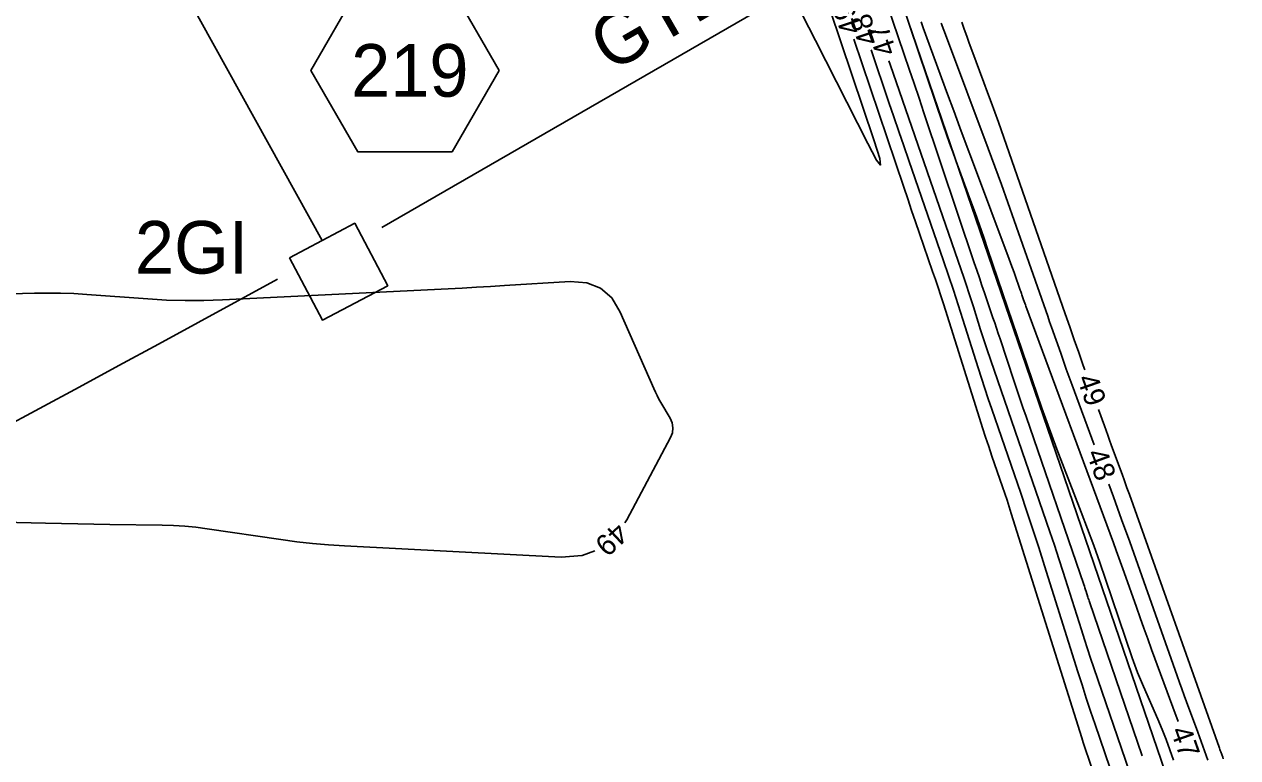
# Model space of a CAD drawing. Extents: x 2384780 to 2405861, y 547869 to 573706.
# Drawn here: x 2391704.7 to 2391820.1, y 552887.6 to 552957.3 of the extents above; entities that cross this region are included whole.
import ezdxf

# ---------------------------------------------------------------- set-up
doc = ezdxf.new("R2010")
doc.units = 0
for name, color, linetype in [('Breaklines', 7, 'Continuous'), ('Old_Level_12', 7, 'Continuous'), ('Old_Level_5', 7, 'Continuous'), ('Old_Level_60', 7, 'Continuous'), ('Old_Level_61', 7, 'Continuous'), ('Sheet Plan CELL', 7, 'Continuous')]:
    doc.layers.add(name, color=color, linetype=linetype)

msp = doc.modelspace()

# ---------------------------------------------------------------- linework, layer by layer
at = {"layer": 'Breaklines'}
for p, q in [((2391820.056, 552866.099), (2391754.1115, 553058.7325)), ((2391733.0265, 552936.75525), (2391691.145, 553012.541))]:
    msp.add_line(p, q, dxfattribs=at)
msp.add_lwpolyline([(2391729.92225, 552935.11175), (2391736.13075, 552938.39875), (2391739.2715, 552932.4665), (2391733.06825, 552929.1965)], close=True, dxfattribs=at)
at = {"layer": 'Old_Level_12'}
msp.add_lwpolyline([(2391749.86575, 552952.93425), (2391745.39125, 552960.68425), (2391736.44225, 552960.68425), (2391731.96775, 552952.93425), (2391736.44225, 552945.18425), (2391745.39125, 552945.18425)], close=True, dxfattribs=at)
at = {"layer": 'Old_Level_5'}
msp.add_arc((2390350.00532, 555442.22291), 2863, 287.79675278, 298.78936111, dxfattribs=at)
at = {"layer": 'Old_Level_60'}
for points in [[(2391786.1685, 552960.912), (2391788.366, 552954.45175), (2391788.83625, 552953.067), (2391789.30475, 552951.682), (2391789.772, 552950.29625), (2391790.23775, 552948.91025), (2391795.01825, 552934.655), (2391795.26025, 552933.93475), (2391795.503, 552933.215), (2391795.7465, 552932.49525), (2391795.99075, 552931.77575), (2391796.79, 552929.42625), (2391796.961, 552928.92275), (2391797.13075, 552928.41875), (2391797.29975, 552927.9145), (2391797.46775, 552927.41), (2391798.78525, 552923.4405), (2391799.0685, 552922.59025), (2391799.35425, 552921.74075), (2391799.64225, 552920.892), (2391799.93275, 552920.044), (2391805.42875, 552904.05975), (2391805.48475, 552903.89525), (2391805.5395, 552903.7305), (2391805.59325, 552903.565), (2391805.646, 552903.3995), (2391805.816, 552902.858), (2391805.85275, 552902.742), (2391805.8905, 552902.62625), (2391805.92875, 552902.51075), (2391805.96775, 552902.3955), (2391810.9695, 552887.7755)], [(2391813.94775, 552887.3565), (2391813.61575, 552888.343), (2391813.258, 552889.32), (2391812.87475, 552890.28725), (2391812.46625, 552891.24475), (2391811.08975, 552894.35675), (2391810.80225, 552895.0265), (2391810.53, 552895.702), (2391810.27275, 552896.38375), (2391810.0305, 552897.07125), (2391807.487, 552904.55525), (2391806.93425, 552906.15625), (2391806.36575, 552907.7515), (2391805.78175, 552909.34125), (2391805.18225, 552910.92525), (2391802.87275, 552916.93925), (2391802.384, 552918.23025), (2391801.908, 552919.526), (2391801.44475, 552920.826), (2391800.99425, 552922.13075), (2391796.3195, 552935.88275), (2391795.91625, 552937.057), (2391795.50575, 552938.22875), (2391795.08775, 552939.398), (2391794.6625, 552940.5645), (2391793.26125, 552944.37125), (2391792.96375, 552945.18775), (2391792.671, 552946.00625), (2391792.38375, 552946.8265), (2391792.10125, 552947.6485), (2391788.877, 552957.1325)], [(2391814.3855, 552891.0375), (2391813.8895, 552892.39975), (2391811.87525, 552897.88325), (2391811.50825, 552898.8865), (2391811.144, 552899.891), (2391810.78275, 552900.89625), (2391810.424, 552901.9025), (2391809.25725, 552905.1915), (2391809.006, 552905.896), (2391808.7525, 552906.5995), (2391808.49675, 552907.30225), (2391808.23875, 552908.00425), (2391799.9245, 552930.51225), (2391799.8695, 552930.662), (2391799.81525, 552930.81175), (2391799.76175, 552930.962), (2391799.709, 552931.11225), (2391799.53725, 552931.60375), (2391799.5005, 552931.70925), (2391799.46375, 552931.8145), (2391799.427, 552931.91975), (2391799.39025, 552932.02525), (2391798.833, 552933.621), (2391798.7125, 552933.96275), (2391798.59025, 552934.3035), (2391798.466, 552934.64375), (2391798.34, 552934.98325), (2391794.84525, 552944.3085), (2391794.2505, 552945.899), (2391793.658, 552947.4905), (2391793.068, 552949.0825), (2391792.48025, 552950.67575), (2391790.1635, 552956.97), (2391789.95525, 552957.5415)], [(2391806.40625, 552917.351), (2391804.312, 552923.02025), (2391804.03575, 552923.77325), (2391803.76275, 552924.5275), (2391803.4935, 552925.283), (2391803.22725, 552926.0395), (2391802.36375, 552928.513), (2391802.17875, 552929.04325), (2391801.9935, 552929.57325), (2391801.8085, 552930.10325), (2391801.6235, 552930.63325), (2391798.81975, 552938.6635), (2391798.21425, 552940.3825), (2391797.59875, 552942.098), (2391796.97375, 552943.81), (2391796.339, 552945.51825), (2391792.37875, 552956.08575), (2391791.88375, 552957.41725)], [(2391805.52, 552924.4775), (2391805.38, 552924.87875), (2391804.95175, 552926.10525), (2391804.5235, 552927.332), (2391804.09525, 552928.5585), (2391803.667, 552929.785), (2391797.306, 552948.00375), (2391796.9715, 552948.95325), (2391796.6315, 552949.901), (2391796.28625, 552950.84675), (2391795.9355, 552951.7905), (2391794.78125, 552954.8705), (2391794.53575, 552955.531), (2391794.29375, 552956.193), (2391794.0555, 552956.85625), (2391793.82075, 552957.52075)], [(2391783.563, 552955.91025), (2391788.3155, 552941.8295), (2391788.6885, 552940.727), (2391789.06375, 552939.625), (2391789.4405, 552938.5235), (2391789.81925, 552937.42275), (2391791.05925, 552933.82775), (2391791.3225, 552933.05675), (2391791.5805, 552932.28375), (2391791.8335, 552931.50925), (2391792.08125, 552930.733), (2391795.51125, 552919.86875), (2391795.79975, 552918.96525), (2391796.094, 552918.0635), (2391796.39375, 552917.16375), (2391796.69925, 552916.26575), (2391797.707, 552913.3355), (2391797.92075, 552912.707), (2391798.13025, 552912.077), (2391798.3355, 552911.4455), (2391798.5365, 552910.81275), (2391805.2335, 552889.49), (2391805.38125, 552889.02475), (2391805.532, 552888.5605), (2391805.6855, 552888.097), (2391805.842, 552887.63475), (2391806.35825, 552886.12575)], [(2391785.22425, 552954.89275), (2391786.91075, 552949.8955), (2391787.37875, 552948.51275), (2391787.84925, 552947.13075), (2391788.32175, 552945.7495), (2391788.79675, 552944.369), (2391792.08775, 552934.82825), (2391792.563, 552933.43525), (2391793.02925, 552932.0395), (2391793.486, 552930.6405), (2391793.93375, 552929.2385), (2391795.38125, 552924.65375), (2391795.6945, 552923.67225), (2391796.014, 552922.693), (2391796.33975, 552921.7155), (2391796.6715, 552920.74025), (2391799.426, 552912.72975), (2391800.01025, 552911.0115), (2391800.58325, 552909.28925), (2391801.1445, 552907.56325), (2391801.69425, 552905.83325), (2391804.856, 552895.766), (2391805.2555, 552894.508), (2391805.66275, 552893.25275), (2391806.07825, 552892), (2391806.5015, 552890.75), (2391807.89725, 552886.6705)], [(2391786.90275, 552953.842), (2391787.01925, 552953.50375), (2391794.04425, 552933.138), (2391794.27225, 552932.47025), (2391794.49575, 552931.801), (2391794.71475, 552931.13025), (2391794.92925, 552930.458), (2391795.62325, 552928.26), (2391795.7735, 552927.7895), (2391795.92675, 552927.32), (2391796.08275, 552926.8515), (2391796.242, 552926.38375), (2391802.197, 552909.0645), (2391802.63125, 552907.78775), (2391803.05675, 552906.50825), (2391803.47375, 552905.226), (2391803.88225, 552903.94075), (2391805.20225, 552899.738), (2391805.488, 552898.83825), (2391805.77925, 552897.9405), (2391806.0765, 552897.0445), (2391806.379, 552896.15025), (2391809.7635, 552886.258)], [(2391761.7995, 552909.92475), (2391761.98925, 552910.19725), (2391766.135, 552918.02275), (2391766.31875, 552918.4895), (2391766.37375, 552918.95375), (2391766.3, 552919.4155), (2391766.09775, 552919.8745), (2391765.22675, 552921.36975), (2391765.04475, 552921.6925), (2391764.872, 552922.02025), (2391764.709, 552922.3525), (2391764.555, 552922.68975), (2391761.3665, 552929.951), (2391760.55675, 552931.2995), (2391759.4935, 552932.23275), (2391758.17725, 552932.75075), (2391756.60775, 552932.85375), (2391750.36975, 552932.46875), (2391749.03275, 552932.3885), (2391747.69575, 552932.31225), (2391746.3585, 552932.2405), (2391745.021, 552932.17275), (2391723.55, 552931.12175), (2391721.77525, 552931.062), (2391720.00125, 552931.0565), (2391718.228, 552931.10525), (2391716.45525, 552931.20825), (2391710.66575, 552931.63325), (2391709.42475, 552931.70875), (2391708.183, 552931.75325), (2391706.9405, 552931.76625), (2391705.6975, 552931.748), (2391684.92875, 552931.1845)], [(2391818.684, 552887.482), (2391818.62625, 552887.6405), (2391818.43625, 552888.15775), (2391818.39575, 552888.2685), (2391818.3555, 552888.3795), (2391818.31575, 552888.4905), (2391818.276, 552888.60175), (2391809.76225, 552912.5995), (2391809.5295, 552913.25225), (2391809.29475, 552913.904), (2391809.05775, 552914.55525), (2391808.81875, 552915.2055), (2391808.03425, 552917.32875), (2391807.86725, 552917.78425), (2391807.70225, 552918.24025), (2391807.53925, 552918.697), (2391807.3785, 552919.15475), (2391806.8385, 552920.70125)], [(2391660.5635, 552918.4135), (2391673, 552913.35025), (2391676.53475, 552912.0925), (2391680.139, 552911.16875), (2391683.81275, 552910.5795), (2391687.55575, 552910.32425), (2391706.75225, 552909.8765), (2391708.27875, 552909.84275), (2391709.80525, 552909.813), (2391711.332, 552909.787), (2391712.85875, 552909.765), (2391717.84625, 552909.699), (2391718.9135, 552909.66725), (2391719.978, 552909.59975), (2391721.0395, 552909.49675), (2391722.09825, 552909.35825), (2391729.1165, 552908.3205), (2391730.622, 552908.11625), (2391732.13125, 552907.948), (2391733.64425, 552907.81575), (2391735.16075, 552907.71975), (2391755.75625, 552906.6605), (2391757.73725, 552906.79975), (2391758.938, 552907.249)], [(2391817.2065, 552887.36725), (2391816.8955, 552888.2535), (2391816.57925, 552889.13775), (2391816.258, 552890.02025), (2391815.2, 552892.9), (2391814.97425, 552893.51725), (2391814.75025, 552894.13525), (2391814.52775, 552894.754), (2391814.307, 552895.37325), (2391810.554, 552905.95175), (2391809.7875, 552908.10125), (2391809.01425, 552910.24825), (2391808.23375, 552912.393), (2391807.79075, 552913.5985)]]:
    msp.add_lwpolyline(points, dxfattribs=at)
at = {"layer": 'Old_Level_61'}
msp.add_lwpolyline([(2391778.65325, 552958.253), (2391779.91775, 552955.7615), (2391784.88675, 552945.97), (2391785.7245, 552944.41275), (2391786.10775, 552943.93725), (2391786.03675, 552944.54375), (2391785.5115, 552946.23225), (2391781.28875, 552958.74325)], dxfattribs=at)
at = {"layer": 'Sheet Plan CELL'}
msp.add_line((2391787.167, 552965.963), (2391738.7015, 552938.00375), dxfattribs=at)

# ---------------------------------------------------------------- texts
at = {"layer": 'Old_Level_12'}
msp.add_text('219', height=4.999999, dxfattribs=at).set_placement((2391735.79345, 552950.43425))
at = {"layer": 'Old_Level_5'}
msp.add_text('GTD', height=5, rotation=29.9802056, dxfattribs=at).set_placement((2391760.43111, 552952.6678))
msp.add_text('2GI', height=4.999999, dxfattribs=at).set_placement((2391715.24134, 552933.61688))
at = {"layer": 'Old_Level_60'}
for s, rotation, p in [('49', 108.6649972, (2391784.3445, 552956.72275)), ('48', 108.6914611, (2391786.01325, 552955.6835)), ('47', 108.7349278, (2391787.665, 552954.69925)), ('49', 289.2462833, (2391804.74725, 552923.65725)), ('48', 290.2509861, (2391805.6405, 552916.53975)), ('49', 223.0800667, (2391760.9815, 552910.0935)), ('47', 289.5049472, (2391813.639, 552890.17175))]:
    msp.add_text(s, height=2, rotation=rotation, dxfattribs=at).set_placement(p)

doc.saveas('drawing.dxf')
